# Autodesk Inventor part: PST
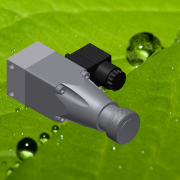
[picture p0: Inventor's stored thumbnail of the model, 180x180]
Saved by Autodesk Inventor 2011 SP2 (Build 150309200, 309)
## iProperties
Created: 2013-12
Part Number: PST
Document SubType Name: Modeling
Designer: dorohin
Density: 1 g/cm^3
Author: dorohin
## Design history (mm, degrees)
node "Твердое тело1"
derived "PST.iam"
node "PSP_.ipt:1"
sketch "ECA_B_10.ipt:1"
node "PSP_-G14.ipt:1"
sketch "Винт ГОСТ 11738-84 M 5x45:1"
sketch "Винт ГОСТ 11738-84 M 5x45:2"
sketch "Винт ГОСТ 11738-84 M 5x45:3"
sketch "Винт ГОСТ 11738-84 M 5x45:4"
